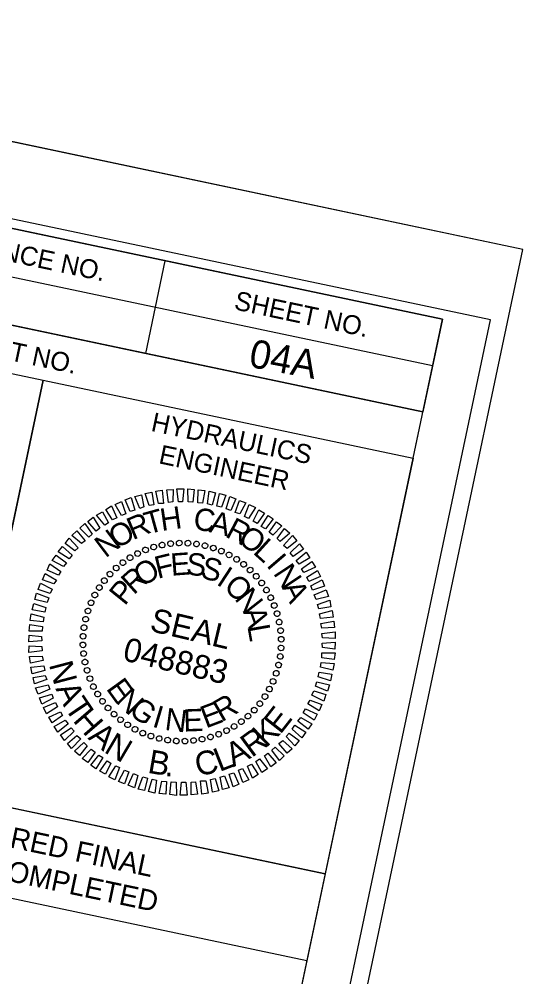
# Model space of a CAD drawing. Extents: x 1636389 to 1804395, y 659763 to 844521.
# Drawn here: x 1638129.5 to 1638262.7, y 843981.4 to 844234.9 of the extents above; entities that cross this region are included whole.
import ezdxf

# ---------------------------------------------------------------- set-up
doc = ezdxf.new("R2010")
doc.units = 0
for name, color, linetype in [('Default', 7, 'Continuous'), ('Old_Level_2', 7, 'Continuous'), ('Sheet Cutting Line CELL', 7, 'Continuous'), ('Sheet Data Field CELL', 7, 'Continuous'), ('Sheet Plan CELL', 7, 'Continuous'), ('Sheet Plan Layout CELL', 7, 'Continuous'), ('Sheet Plot Border Inside CELL', 7, 'Continuous'), ('Sheet Plot Border Outside CELL', 7, 'Continuous'), ('Sheet Sticker Exception Certification CELL', 7, 'Continuous')]:
    doc.layers.add(name, color=color, linetype=linetype)

msp = doc.modelspace()

# ---------------------------------------------------------------- linework, layer by layer
at = {"layer": 'Old_Level_2'}
for p, q in [((1638165.07, 844095.15), (1638165.07, 844095.15)), ((1638167.28, 844095.74), (1638167.28, 844095.74)), ((1638169.5, 844096.1), (1638169.5, 844096.1)), ((1638171.78, 844096.25), (1638171.78, 844096.25)), ((1638174.12, 844096.16), (1638174.12, 844096.16)), ((1638176.38, 844095.99), (1638176.38, 844095.99)), ((1638178.64, 844095.55), (1638178.64, 844095.55)), ((1638180.86, 844094.9), (1638180.86, 844094.9)), ((1638158.78, 844092.35), (1638158.78, 844092.35)), ((1638160.8, 844093.52), (1638160.8, 844093.52)), ((1638162.87, 844094.4), (1638162.87, 844094.4)), ((1638182.97, 844094.06), (1638182.97, 844094.06)), ((1638185.02, 844093.13), (1638185.02, 844093.13)), ((1638156.9, 844091.1), (1638156.9, 844091.1)), ((1638187.01, 844091.95), (1638187.01, 844091.95)), ((1638188.85, 844090.58), (1638188.85, 844090.58)), ((1638153.45, 844088.06), (1638153.45, 844088.06)), ((1638155.13, 844089.62), (1638155.13, 844089.62)), ((1638190.62, 844089.12), (1638190.62, 844089.12)), ((1638192.18, 844087.44), (1638192.18, 844087.44)), ((1638151.99, 844086.29), (1638151.99, 844086.29)), ((1638193.66, 844085.67), (1638193.66, 844085.67)), ((1638149.44, 844082.46), (1638149.44, 844082.46)), ((1638150.62, 844084.45), (1638150.62, 844084.45)), ((1638194.91, 844083.8), (1638194.91, 844083.8)), ((1638148.51, 844080.42), (1638148.51, 844080.42)), ((1638196.07, 844081.77), (1638196.07, 844081.77)), ((1638196.96, 844079.71), (1638196.96, 844079.71)), ((1638147.67, 844078.3), (1638147.67, 844078.3)), ((1638197.71, 844077.51), (1638197.71, 844077.51)), ((1638147.03, 844076.08), (1638147.03, 844076.08)), ((1638198.29, 844075.29), (1638198.29, 844075.29)), ((1638146.58, 844073.83), (1638146.58, 844073.83)), ((1638198.66, 844073.07), (1638198.66, 844073.07)), ((1638146.41, 844071.56), (1638146.41, 844071.56)), ((1638172.57, 844070.01), (1638172.57, 844070.01)), ((1638198.81, 844070.79), (1638198.81, 844070.79)), ((1638146.33, 844069.23), (1638146.33, 844069.23)), ((1638146.47, 844066.95), (1638146.47, 844066.95)), ((1638198.72, 844068.45), (1638198.72, 844068.45)), ((1638146.84, 844064.72), (1638146.84, 844064.72)), ((1638198.55, 844066.19), (1638198.55, 844066.19)), ((1638147.42, 844062.51), (1638147.42, 844062.51)), ((1638198.11, 844063.93), (1638198.11, 844063.93)), ((1638148.17, 844060.31), (1638148.17, 844060.31)), ((1638196.62, 844059.6), (1638196.62, 844059.6)), ((1638197.46, 844061.72), (1638197.46, 844061.72)), ((1638149.06, 844058.24), (1638149.06, 844058.24)), ((1638195.69, 844057.56), (1638195.69, 844057.56)), ((1638150.22, 844056.22), (1638150.22, 844056.22)), ((1638151.47, 844054.34), (1638151.47, 844054.34)), ((1638194.51, 844055.57), (1638194.51, 844055.57)), ((1638152.96, 844052.57), (1638152.96, 844052.57)), ((1638191.68, 844051.96), (1638191.68, 844051.96)), ((1638193.14, 844053.73), (1638193.14, 844053.73)), ((1638154.51, 844050.89), (1638154.51, 844050.89)), ((1638156.28, 844049.43), (1638156.28, 844049.43)), ((1638190, 844050.4), (1638190, 844050.4)), ((1638158.12, 844048.07), (1638158.12, 844048.07)), ((1638160.11, 844046.88), (1638160.11, 844046.88)), ((1638186.35, 844047.66), (1638186.35, 844047.66)), ((1638188.23, 844048.91), (1638188.23, 844048.91)), ((1638162.16, 844045.95), (1638162.16, 844045.95)), ((1638164.28, 844045.11), (1638164.28, 844045.11)), ((1638166.49, 844044.47), (1638166.49, 844044.47)), ((1638177.85, 844044.28), (1638177.85, 844044.28)), ((1638180.07, 844044.87), (1638180.07, 844044.87)), ((1638182.26, 844045.62), (1638182.26, 844045.62)), ((1638184.33, 844046.5), (1638184.33, 844046.5)), ((1638168.75, 844044.03), (1638168.75, 844044.03)), ((1638171.01, 844043.85), (1638171.01, 844043.85)), ((1638173.35, 844043.77), (1638173.35, 844043.77)), ((1638175.63, 844043.91), (1638175.63, 844043.91))]:
    msp.add_line(p, q, dxfattribs=at)
for points in [[(1638166.31, 844106.71), (1638165.63, 844109.96), (1638167.3, 844110.24), (1638167.66, 844106.73)], [(1638168.99, 844106.98), (1638168.49, 844110.3), (1638170.18, 844110.41), (1638170.15, 844107.1)], [(1638171.59, 844107.1), (1638171.22, 844110.56), (1638173.04, 844110.53), (1638172.72, 844107.12)], [(1638174.17, 844107.13), (1638174.07, 844110.58), (1638175.78, 844110.36), (1638175.43, 844107.01)], [(1638176.69, 844106.9), (1638176.84, 844110.29), (1638178.62, 844110.11), (1638177.95, 844106.78)], [(1638158.84, 844104.6), (1638157.52, 844107.62), (1638159.06, 844108.3), (1638160.1, 844104.96)], [(1638161.37, 844105.38), (1638160.08, 844108.55), (1638161.84, 844109.02), (1638162.47, 844105.78)], [(1638163.83, 844106.13), (1638162.82, 844109.34), (1638164.56, 844109.71), (1638165.06, 844106.34)], [(1638179.3, 844106.59), (1638179.77, 844109.97), (1638181.44, 844109.55), (1638180.51, 844106.27)], [(1638181.74, 844106), (1638182.46, 844109.32), (1638184.14, 844108.9), (1638182.95, 844105.69)], [(1638184.26, 844105.29), (1638185.19, 844108.57), (1638186.81, 844107.89), (1638185.44, 844104.82)], [(1638186.62, 844104.35), (1638187.79, 844107.51), (1638189.42, 844106.89), (1638187.81, 844103.92)], [(1638154.17, 844102.35), (1638152.42, 844105.09), (1638153.91, 844106.05), (1638155.3, 844102.86)], [(1638156.56, 844103.49), (1638154.9, 844106.42), (1638156.52, 844107.19), (1638157.68, 844103.94)], [(1638189.1, 844103.21), (1638190.34, 844106.42), (1638191.99, 844105.63), (1638190.12, 844102.72)], [(1638191.41, 844102.01), (1638192.87, 844105.01), (1638194.34, 844104.15), (1638192.4, 844101.42)], [(1638149.88, 844099.39), (1638147.66, 844101.96), (1638149.08, 844103.04), (1638150.8, 844100.15)], [(1638152.1, 844100.94), (1638149.95, 844103.6), (1638151.48, 844104.5), (1638153.09, 844101.57)], [(1638193.5, 844100.59), (1638195.38, 844103.55), (1638196.68, 844102.62), (1638194.6, 844099.97)], [(1638147.92, 844097.78), (1638145.55, 844100.12), (1638146.84, 844101.39), (1638148.8, 844098.61)], [(1638195.59, 844099.12), (1638197.53, 844101.85), (1638198.95, 844100.79), (1638196.59, 844098.31)], [(1638197.68, 844097.43), (1638199.7, 844100.04), (1638201.04, 844098.83), (1638198.52, 844096.6)], [(1638144.24, 844094.15), (1638141.61, 844096.06), (1638142.72, 844097.48), (1638145.06, 844094.98)], [(1638145.94, 844096.07), (1638143.42, 844098.23), (1638144.76, 844099.44), (1638146.96, 844096.81)], [(1638199.37, 844095.61), (1638201.81, 844098.18), (1638202.9, 844096.82), (1638200.36, 844094.75)], [(1638142.7, 844092.02), (1638139.79, 844093.89), (1638140.91, 844095.3), (1638143.46, 844093.03)], [(1638201.13, 844093.62), (1638203.64, 844096.02), (1638204.72, 844094.6), (1638201.94, 844092.69)], [(1638141.19, 844090), (1638138.22, 844091.61), (1638139.23, 844093.05), (1638141.98, 844090.95)], [(1638202.72, 844091.61), (1638205.4, 844093.81), (1638206.36, 844092.31), (1638203.53, 844090.63)], [(1638139.88, 844087.71), (1638136.86, 844089.07), (1638137.59, 844090.68), (1638140.53, 844088.7)], [(1638204.17, 844089.42), (1638206.89, 844091.34), (1638207.85, 844089.85), (1638204.76, 844088.44)], [(1638138.68, 844085.41), (1638135.61, 844086.51), (1638136.34, 844088.17), (1638139.33, 844086.39)], [(1638205.56, 844087.19), (1638208.41, 844088.97), (1638209.18, 844087.36), (1638206.05, 844086.01)], [(1638137.7, 844082.89), (1638134.5, 844083.91), (1638135.09, 844085.61), (1638138.23, 844084.06)], [(1638206.65, 844084.86), (1638209.63, 844086.46), (1638210.27, 844084.77), (1638207.05, 844083.76)], [(1638136.91, 844080.5), (1638133.61, 844081.32), (1638134.09, 844082.99), (1638137.28, 844081.7)], [(1638207.52, 844082.48), (1638210.65, 844083.83), (1638211.29, 844082.08), (1638208.01, 844081.3)], [(1638136.3, 844077.95), (1638132.95, 844078.53), (1638133.33, 844080.26), (1638136.57, 844079.18)], [(1638208.36, 844079.94), (1638211.61, 844081.1), (1638211.93, 844079.37), (1638208.76, 844078.83)], [(1638135.79, 844075.39), (1638132.38, 844075.71), (1638132.66, 844077.46), (1638135.96, 844076.64)], [(1638208.9, 844077.52), (1638212.25, 844078.39), (1638212.55, 844076.61), (1638209.16, 844076.28)], [(1638135.56, 844072.87), (1638132.09, 844072.88), (1638132.31, 844074.65), (1638135.63, 844074.14)], [(1638209.29, 844074.92), (1638212.7, 844075.56), (1638212.91, 844073.86), (1638209.57, 844073.73)], [(1638209.57, 844072.29), (1638213.1, 844072.75), (1638213.03, 844070.99), (1638209.69, 844071.14)], [(1638135.49, 844070.32), (1638132.05, 844070.05), (1638132.13, 844071.85), (1638135.41, 844071.46)], [(1638209.65, 844069.7), (1638213.08, 844069.97), (1638213, 844068.16), (1638209.72, 844068.56)], [(1638135.56, 844067.73), (1638132.03, 844067.27), (1638132.1, 844069.02), (1638135.44, 844068.88)], [(1638209.57, 844067.15), (1638213.05, 844067.14), (1638212.82, 844065.37), (1638209.51, 844065.88)], [(1638135.84, 844065.1), (1638132.43, 844064.45), (1638132.22, 844066.16), (1638135.57, 844066.28)], [(1638209.34, 844064.63), (1638212.75, 844064.31), (1638212.47, 844062.55), (1638209.17, 844063.38)], [(1638136.23, 844062.5), (1638132.89, 844061.63), (1638132.58, 844063.41), (1638135.97, 844063.73)], [(1638208.83, 844062.06), (1638212.18, 844061.49), (1638211.8, 844059.75), (1638208.56, 844060.84)], [(1638136.78, 844060.08), (1638133.52, 844058.92), (1638133.21, 844060.64), (1638136.37, 844061.18)], [(1638208.22, 844059.52), (1638211.52, 844058.69), (1638211.05, 844057.03), (1638207.85, 844058.32)], [(1638137.61, 844057.54), (1638134.48, 844056.19), (1638133.84, 844057.94), (1638137.12, 844058.72)], [(1638207.43, 844057.13), (1638210.63, 844056.1), (1638210.05, 844054.41), (1638206.9, 844055.96)], [(1638138.48, 844055.15), (1638135.51, 844053.56), (1638134.86, 844055.25), (1638138.08, 844056.26)], [(1638206.45, 844054.61), (1638209.53, 844053.51), (1638208.79, 844051.85), (1638205.81, 844053.63)], [(1638139.58, 844052.83), (1638136.72, 844051.04), (1638135.95, 844052.66), (1638139.08, 844054)], [(1638205.25, 844052.3), (1638208.27, 844050.95), (1638207.54, 844049.34), (1638204.6, 844051.32)], [(1638140.96, 844050.6), (1638138.24, 844048.68), (1638137.28, 844050.17), (1638140.37, 844051.58)], [(1638142.41, 844048.41), (1638139.73, 844046.21), (1638138.77, 844047.7), (1638141.61, 844049.38)], [(1638203.94, 844050.02), (1638206.91, 844048.41), (1638205.9, 844046.97), (1638203.15, 844049.07)], [(1638144, 844046.4), (1638141.5, 844044), (1638140.41, 844045.42), (1638143.19, 844047.32)], [(1638202.43, 844048), (1638205.34, 844046.13), (1638204.23, 844044.71), (1638201.67, 844046.98)], [(1638145.76, 844044.41), (1638143.32, 844041.83), (1638142.23, 844043.2), (1638144.77, 844045.26)], [(1638200.89, 844045.87), (1638203.53, 844043.96), (1638202.41, 844042.54), (1638200.07, 844045.03)], [(1638147.45, 844042.59), (1638145.43, 844039.98), (1638144.09, 844041.18), (1638146.61, 844043.42)], [(1638149.54, 844040.9), (1638147.61, 844038.17), (1638146.18, 844039.23), (1638148.54, 844041.71)], [(1638197.21, 844042.24), (1638199.59, 844039.89), (1638198.29, 844038.63), (1638196.33, 844041.41)], [(1638199.19, 844043.94), (1638201.71, 844041.78), (1638200.38, 844040.58), (1638198.17, 844043.2)], [(1638151.63, 844039.43), (1638149.75, 844036.47), (1638148.45, 844037.39), (1638150.53, 844040.04)], [(1638193.04, 844039.08), (1638195.18, 844036.42), (1638193.65, 844035.52), (1638192.04, 844038.44)], [(1638195.25, 844040.63), (1638197.47, 844038.06), (1638196.06, 844036.97), (1638194.33, 844039.87)], [(1638153.73, 844038), (1638152.27, 844035.01), (1638150.79, 844035.86), (1638152.73, 844038.6)], [(1638156.03, 844036.8), (1638154.79, 844033.59), (1638153.15, 844034.38), (1638155.02, 844037.29)], [(1638188.57, 844036.53), (1638190.23, 844033.59), (1638188.62, 844032.82), (1638187.45, 844036.08)], [(1638190.96, 844037.66), (1638192.72, 844034.92), (1638191.22, 844033.97), (1638189.83, 844037.16)], [(1638158.51, 844035.67), (1638157.34, 844032.5), (1638155.71, 844033.13), (1638157.32, 844036.09)], [(1638160.88, 844034.72), (1638159.94, 844031.45), (1638158.33, 844032.13), (1638159.69, 844035.2)], [(1638163.4, 844034.01), (1638162.67, 844030.69), (1638160.99, 844031.11), (1638162.18, 844034.33)], [(1638183.77, 844034.64), (1638185.05, 844031.46), (1638183.29, 844030.99), (1638182.66, 844034.23)], [(1638186.29, 844035.42), (1638187.61, 844032.4), (1638186.07, 844031.72), (1638185.04, 844035.05)], [(1638165.84, 844033.42), (1638165.36, 844030.05), (1638163.69, 844030.47), (1638164.62, 844033.74)], [(1638168.45, 844033.12), (1638168.29, 844029.73), (1638166.51, 844029.9), (1638167.19, 844033.24)], [(1638170.97, 844032.89), (1638171.07, 844029.44), (1638169.35, 844029.66), (1638169.71, 844033)], [(1638173.54, 844032.91), (1638173.91, 844029.46), (1638172.09, 844029.48), (1638172.41, 844032.89)], [(1638176.14, 844033.04), (1638176.64, 844029.72), (1638174.96, 844029.61), (1638174.99, 844032.92)], [(1638178.82, 844033.31), (1638179.5, 844030.06), (1638177.83, 844029.78), (1638177.48, 844033.28)], [(1638181.3, 844033.89), (1638182.31, 844030.67), (1638180.57, 844030.3), (1638180.08, 844033.68)]]:
    msp.add_lwpolyline(points, close=True, dxfattribs=at)
for centre, major_axis in [((1638162.89, 844094.39), (-0.278, 0.7)), ((1638165.05, 844095.14), (-0.216, 0.721)), ((1638167.27, 844095.7), (-0.152, 0.737)), ((1638169.53, 844096.06), (-0.087, 0.748)), ((1638171.81, 844096.23), (-0.022, 0.753)), ((1638174.1, 844096.19), (0.044, 0.752)), ((1638176.38, 844095.96), (0.109, 0.745)), ((1638178.62, 844095.53), (0.174, 0.733)), ((1638180.83, 844094.9), (0.237, 0.715)), ((1638182.96, 844094.09), (0.299, 0.691)), ((1638158.81, 844092.34), (-0.395, 0.641)), ((1638160.8, 844093.45), (-0.338, 0.673)), ((1638185.02, 844093.09), (0.358, 0.663)), ((1638186.99, 844091.92), (0.414, 0.629)), ((1638155.14, 844089.61), (-0.5, 0.563)), ((1638156.91, 844091.05), (-0.449, 0.604)), ((1638188.84, 844090.58), (0.467, 0.59)), ((1638190.57, 844089.08), (0.517, 0.547)), ((1638153.5, 844088.01), (-0.547, 0.517)), ((1638192.17, 844087.44), (0.563, 0.5)), ((1638150.66, 844084.43), (-0.629, 0.414)), ((1638152, 844086.28), (-0.59, 0.467)), ((1638193.61, 844085.66), (0.604, 0.449)), ((1638149.49, 844082.47), (-0.663, 0.358)), ((1638194.89, 844083.77), (0.641, 0.395)), ((1638196.01, 844081.77), (0.673, 0.338)), ((1638148.49, 844080.41), (-0.691, 0.299)), ((1638196.94, 844079.68), (0.7, 0.278)), ((1638147.67, 844078.27), (-0.715, 0.237)), ((1638197.7, 844077.52), (0.721, 0.216)), ((1638146.62, 844073.82), (-0.745, 0.109)), ((1638147.05, 844076.07), (-0.733, 0.174)), ((1638198.25, 844075.3), (0.737, 0.152)), ((1638146.38, 844071.54), (-0.752, 0.044)), ((1638198.62, 844073.04), (0.748, 0.087)), ((1638146.35, 844069.26), (-0.753, -0.022)), ((1638198.78, 844070.76), (0.753, 0.022)), ((1638146.51, 844066.97), (-0.748, -0.087)), ((1638198.52, 844066.2), (0.745, -0.109)), ((1638198.75, 844068.47), (0.752, -0.044)), ((1638146.88, 844064.71), (-0.737, -0.152)), ((1638198.08, 844063.95), (0.733, -0.174)), ((1638147.44, 844062.5), (-0.721, -0.216)), ((1638197.46, 844061.75), (0.715, -0.237)), ((1638148.19, 844060.33), (-0.7, -0.278)), ((1638196.64, 844059.61), (0.691, -0.299)), ((1638149.12, 844058.25), (-0.673, -0.338)), ((1638150.24, 844056.25), (-0.641, -0.395)), ((1638195.65, 844057.55), (0.663, -0.358)), ((1638151.52, 844054.35), (-0.604, -0.449)), ((1638193.13, 844053.73), (0.59, -0.467)), ((1638194.47, 844055.59), (0.629, -0.414)), ((1638152.97, 844052.58), (-0.563, -0.5)), ((1638154.56, 844050.94), (-0.517, -0.547)), ((1638191.64, 844052), (0.547, -0.517)), ((1638156.29, 844049.44), (-0.467, -0.59)), ((1638188.22, 844048.96), (0.449, -0.604)), ((1638189.99, 844050.41), (0.5, -0.563)), ((1638158.15, 844048.1), (-0.414, -0.629)), ((1638160.11, 844046.93), (-0.358, -0.663)), ((1638162.17, 844045.93), (-0.299, -0.691)), ((1638184.33, 844046.57), (0.338, -0.673)), ((1638186.33, 844047.68), (0.395, -0.641)), ((1638164.31, 844045.12), (-0.237, -0.715)), ((1638166.51, 844044.49), (-0.174, -0.733)), ((1638168.75, 844044.06), (-0.109, -0.745)), ((1638171.03, 844043.83), (-0.044, -0.752)), ((1638173.32, 844043.79), (0.022, -0.753)), ((1638175.6, 844043.96), (0.087, -0.748)), ((1638177.86, 844044.32), (0.152, -0.737)), ((1638180.08, 844044.88), (0.216, -0.721)), ((1638182.24, 844045.63), (0.278, -0.7))]:
    msp.add_ellipse(centre, major_axis=major_axis, ratio=0.999708, dxfattribs=at)
at = {"layer": 'Sheet Cutting Line CELL'}
msp.add_line((1638262.69, 844173.95), (1636615.46, 844521.48), dxfattribs=at)
at = {"layer": 'Sheet Plan CELL'}
for p, q in [((1638043.08, 844184.49), (1638238.82, 844143.18)), ((1638040.5, 844172.22), (1638236.24, 844130.95)), ((1638040.5, 844172.22), (1638236.24, 844130.95)), ((1638167.98, 844170.89), (1638162.87, 844146.42)), ((1638135.82, 844139.35), (1638112.61, 844029.31))]:
    msp.add_line(p, q, dxfattribs=at)
for points in [[(1638241.44, 844155.45), (1636773.71, 844465.11), (1636556.96, 843437.72), (1638024.67, 843128.08)], [(1636556.96, 843437.72), (1636773.69, 844465.09), (1638045.68, 844196.77), (1638014.71, 844049.94), (1638210.44, 844008.63), (1638024.67, 843128.08)], [(1638045.68, 844196.77), (1638241.44, 844155.45), (1638236.24, 844130.95), (1638040.5, 844172.22)], [(1638037.92, 844160), (1638135.82, 844139.35), (1638112.59, 844029.26), (1638014.71, 844049.94)], [(1638135.82, 844139.35), (1638233.65, 844118.72), (1638210.44, 844008.63), (1638112.59, 844029.26)]]:
    msp.add_lwpolyline(points, close=True, dxfattribs=at)
at = {"layer": 'Sheet Plan Layout CELL'}
msp.add_lwpolyline([(1637963.65, 843997.92), (1638197.77, 843948.52), (1638241.46, 844155.45), (1638007.31, 844204.85)], close=True, dxfattribs=at)
at = {"layer": 'Sheet Plot Border Inside CELL'}
msp.add_lwpolyline([(1636406.26, 843466.95), (1638036.37, 843123.05), (1638254.16, 844155.31), (1636624.05, 844499.23)], close=True, dxfattribs=at)
at = {"layer": 'Sheet Plot Border Outside CELL'}
msp.add_lwpolyline([(1636389.41, 843450.07), (1638036.65, 843102.54), (1638262.69, 844173.95), (1636615.46, 844521.48)], close=True, dxfattribs=at)
at = {"layer": 'Sheet Sticker Exception Certification CELL'}
for p, q in [((1638014.71, 844049.94), (1638210.44, 844008.64)), ((1638014.71, 844049.94), (1638210.44, 844008.64)), ((1638205.59, 843985.65), (1638009.86, 844026.94)), ((1638205.59, 843985.65), (1638009.86, 844026.94)), ((1638210.44, 844008.63), (1638205.59, 843985.63)), ((1638210.44, 844008.63), (1638205.59, 843985.63))]:
    msp.add_line(p, q, dxfattribs=at)

# ---------------------------------------------------------------- texts
at = {"layer": 'Default'}
for s, rotation, p in [('N', 284.7214, (1638137.32, 844064.1)), ('A', 295.3332, (1638139, 844057.7)), ('T', 304.0795, (1638141.26, 844052.74)), ('H', 310.8074, (1638143.49, 844049.19)), ('E', 51.864, (1638198.55, 844045.38)), ('K', 43.6681, (1638194.78, 844041.93)), ('A', 320.6853, (1638147.48, 844044.5)), ('R', 36.2674, (1638190.99, 844039.3)), ('N', 329.4316, (1638151.65, 844040.98)), ('L', 21.3131, (1638182.46, 844035.59)), ('A', 27.5211, (1638186.11, 844036.86)), ('B', 350.1352, (1638163.24, 844035.45)), ('C', 11.8328, (1638176.66, 844034.44)), ('.', 357.75, (1638167.9, 844034.51))]:
    msp.add_text(s, height=6.27, rotation=rotation, dxfattribs=at).set_placement(p)
at = {"layer": 'Old_Level_2'}
for s, height, rotation, p in [('T', 5.9, 15.4639, (1638163.49, 844098.44)), ('H', 5.9, 8.2636, (1638167.17, 844099.4)), ('C', 5.9, 353.864, (1638175.39, 844099.74)), ('R', 5.9, 22.6647, (1638159.52, 844096.95)), ('A', 5.9, 346.6645, (1638179.49, 844099.16)), ('R', 5.9, 332.2652, (1638183.73, 844098.02)), ('O', 5.9, 29.8659, (1638155.3, 844094.56)), ('O', 5.9, 325.0653, (1638186.99, 844096.5)), ('N', 5.9, 37.0677, (1638152.3, 844092.11)), ('L', 5.9, 317.865, (1638191.07, 844093.63)), ('F', 5.9, 13.6112, (1638166.11, 844086.73)), ('E', 5.9, 4.2552, (1638169.72, 844087.55)), ('S', 5.9, 354.8998, (1638173.48, 844087.85)), ('S', 5.9, 345.5446, (1638177.17, 844087.09)), ('I', 5.9, 310.6643, (1638194.67, 844090.27)), ('O', 5.9, 32.3254, (1638162.08, 844084.46)), ('I', 5.9, 326.8338, (1638181.4, 844085.42)), ('N', 5.9, 303.4631, (1638196.52, 844088.21)), ('R', 5.9, 41.6838, (1638159.75, 844082.34)), ('O', 5.9, 317.4776, (1638183.29, 844084.25)), ('P', 5.9, 51.043, (1638157.39, 844079.43)), ('A', 5.9, 296.2613, (1638198.87, 844084.53)), ('N', 5.9, 308.1208, (1638186.26, 844081.46)), ('SEAL', 6.273, 346.6442, (1638163.75, 844073.01)), ('A', 5.9, 289.4044, (1638188.59, 844078.17)), ('L', 5.9, 280.045, (1638189.81, 844074.21)), ('048883', 6.275, 346.6442, (1638156.59, 844065.25)), ('E', 5.9, 305.921, (1638152.31, 844057.69)), ('N', 5.9, 315.2781, (1638154.77, 844054.26)), ('G', 5.9, 324.6344, (1638158.15, 844051.11)), ('E', 5.9, 20.7682, (1638178.85, 844047.11)), ('R', 5.9, 30.1256, (1638183, 844048.72)), ('I', 5.9, 343.3454, (1638164.42, 844047.71)), ('N', 5.9, 352.7005, (1638167.8, 844046.8)), ('E', 5.9, 2.0559, (1638173, 844046.31))]:
    msp.add_text(s, height=height, rotation=rotation, dxfattribs=at).set_placement(p)
at = {"layer": 'Sheet Data Field CELL'}
msp.add_text('04A', height=7.5, rotation=349.3932, dxfattribs=at).set_placement((1638189.94, 844142.92))
at = {"layer": 'Sheet Plan CELL'}
for s, height, p in [('PROJECT REFERENCE NO.', 5.0001, (1638065.6, 844183.65)), ('SHEET NO.', 5, (1638186.09, 844158.11)), ('R/W SHEET NO.', 5.0001, (1638094.38, 844151.46)), ('HYDRAULICS', 5, (1638164.12, 844125.94)), ('ENGINEER', 5, (1638166.16, 844117.37))]:
    msp.add_text(s, height=height, rotation=348.0867, dxfattribs=at).set_placement(p)
at = {"layer": 'Sheet Sticker Exception Certification CELL'}
for s, p in [('DOCUMENT NOT CONSIDERED FINAL', (1638033.2, 844035.46)), ('DOCUMENT NOT CONSIDERED FINAL', (1638033.2, 844035.46)), ('UNLESS ALL SIGNATURES COMPLETED', (1638026.42, 844027.9)), ('UNLESS ALL SIGNATURES COMPLETED', (1638026.42, 844027.9))]:
    msp.add_text(s, height=5.5, rotation=348.0867, dxfattribs=at).set_placement(p)

doc.saveas('drawing.dxf')
